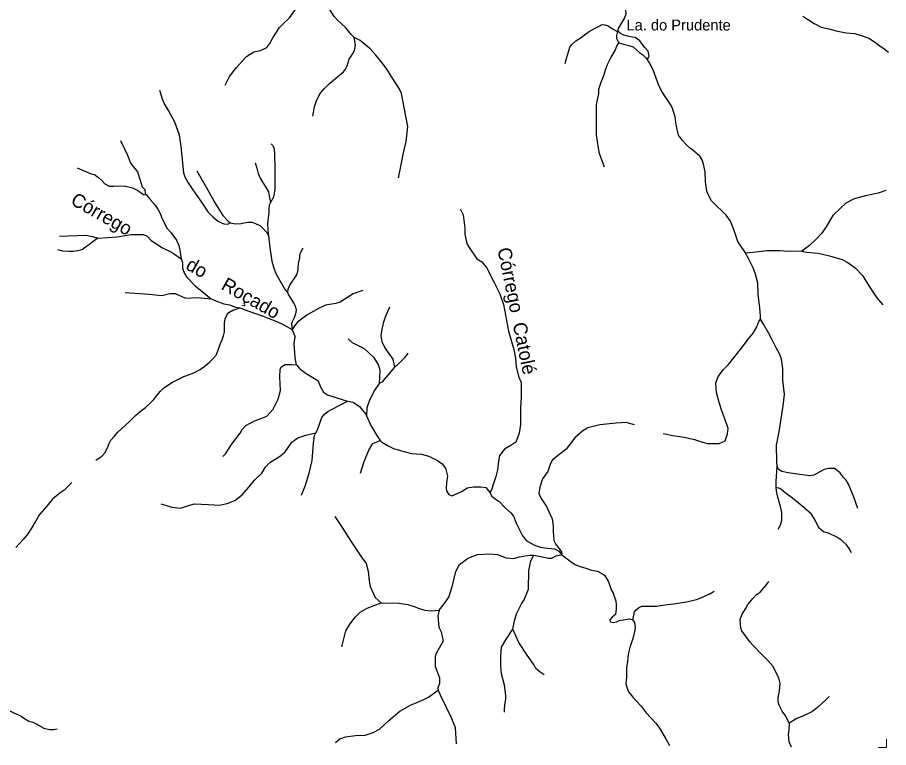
# Model space of a CAD drawing. Extents: x 717.8 to 772.7, y 8672.2 to 8728.
# Drawn here: x 759.54 to 772.27, y 8672.2 to 8682.87 of the extents above; entities that cross this region are included whole.
import ezdxf
from ezdxf.enums import TextEntityAlignment as Align

# ---------------------------------------------------------------- set-up
doc = ezdxf.new("R2010")
doc.units = 0
doc.header["$LTSCALE"] = 0.08
doc.linetypes.add('LONG_DASHED', pattern=[7.5, 6, -1.5])
for name, color, linetype, lineweight in [('3', 7, 'LONG_DASHED', 25), ('63', 7, 'Continuous', 13), ('9', 7, 'LONG_DASHED', 25)]:
    doc.layers.add(name, color=color, linetype=linetype, lineweight=lineweight)
doc.layers.add('61', color=7, linetype='Continuous')

msp = doc.modelspace()

# ---------------------------------------------------------------- linework, layer by layer
at = {"layer": '3'}
for points in [[(768.305, 8682.6583), (768.2931, 8682.6038), (768.2922, 8682.5588), (768.3145, 8682.5074), (768.3239, 8682.4937)], [(768.327, 8682.6503), (768.3193, 8682.6588), (768.305, 8682.6583)], [(768.7235, 8682.2744), (768.7408, 8682.267), (768.7583, 8682.2781), (768.7665, 8682.2996), (768.7658, 8682.3236), (768.7551, 8682.3746), (768.7062, 8682.4249), (768.672, 8682.4696), (768.634, 8682.5227), (768.5643, 8682.5714), (768.5192, 8682.5778), (768.4518, 8682.5927), (768.3969, 8682.6052), (768.3495, 8682.6303), (768.327, 8682.6503)], [(768.3239, 8682.4937), (768.3914, 8682.4758), (768.4691, 8682.4574), (768.5364, 8682.4339), (768.5888, 8682.3897), (768.6337, 8682.3497), (768.6735, 8682.3171), (768.716, 8682.282), (768.7235, 8682.2744)]]:
    msp.add_lwpolyline(points, dxfattribs=at)
at = {"layer": '63'}
msp.add_lwpolyline([(772.1148, 8672.1956), (772.238, 8672.1956), (772.238, 8672.317)], dxfattribs=at)
at = {"layer": '9'}
msp.add_line((761.4201, 8680.2721), (761.4742, 8680.2065), dxfattribs=at)
for points in [[(762.5702, 8681.8758), (762.6352, 8682.0036), (762.738, 8682.1322), (762.8845, 8682.2968), (762.988, 8682.3618), (763.0901, 8682.3839), (763.1789, 8682.4279), (763.2262, 8682.4867), (763.2673, 8682.5691), (763.3103, 8682.6356), (763.3634, 8682.7186), (763.4208, 8682.7739), (763.5135, 8682.8592), (763.586, 8682.9608), (763.6202, 8683.0225), (763.67, 8683.1221), (763.7067, 8683.1896), (763.7322, 8683.2728), (763.7626, 8683.3828), (763.7552, 8683.4633)], [(764.4569, 8682.5737), (764.4186, 8682.6102), (764.3323, 8682.7173), (764.2188, 8682.8192), (764.1669, 8682.8803), (764.0312, 8683.0871), (763.8813, 8683.2897), (763.785, 8683.3978), (763.7552, 8683.4633)], [(768.2321, 8683.4564), (768.2922, 8683.3015), (768.3226, 8683.2381), (768.4015, 8683.1162), (768.4239, 8682.9912), (768.4264, 8682.9122), (768.4077, 8682.86), (768.3189, 8682.7146), (768.305, 8682.6583)], [(771.0141, 8682.8855), (771.1809, 8682.777), (771.2831, 8682.7212), (771.3952, 8682.6987), (771.5005, 8682.6706), (771.6476, 8682.6429), (771.7766, 8682.6292), (771.8825, 8682.5953), (771.9786, 8682.5615), (772.0604, 8682.5109), (772.1392, 8682.4499), (772.2158, 8682.3983), (772.2674, 8682.3602)], [(767.5409, 8682.1933), (767.5584, 8682.2634), (767.5909, 8682.3612), (767.6092, 8682.4288), (767.6363, 8682.47), (767.6964, 8682.5242), (767.7765, 8682.5702), (767.8425, 8682.6238), (767.8929, 8682.6619), (767.9677, 8682.7021), (768.0376, 8682.7373), (768.0815, 8682.76), (768.121, 8682.7588), (768.1673, 8682.7423), (768.2341, 8682.6969), (768.305, 8682.6583)], [(763.8544, 8681.4228), (763.8782, 8681.5571), (763.9062, 8681.6485), (763.9559, 8681.7496), (764.0248, 8681.8289), (764.098, 8681.9013), (764.2991, 8682.0721), (764.3293, 8682.1105), (764.3527, 8682.1575), (764.3847, 8682.2551), (764.4322, 8682.3301), (764.4607, 8682.3835), (764.4745, 8682.4615), (764.4569, 8682.5737)], [(765.1044, 8680.5222), (765.1407, 8680.6872), (765.1758, 8680.8877), (765.2163, 8681.0509), (765.2395, 8681.272), (765.2133, 8681.4249), (765.1489, 8681.7531), (765.1163, 8681.8295), (765.0056, 8681.9938), (764.9365, 8682.1078), (764.8798, 8682.1828), (764.7731, 8682.3153), (764.6916, 8682.4058), (764.5422, 8682.5305), (764.4569, 8682.5737)], [(768.1148, 8680.6772), (768.0423, 8680.8769), (768.0302, 8680.9556), (768.0001, 8681.1493), (768.0004, 8681.3914), (768.0006, 8681.5912), (768.0339, 8681.7547), (768.032, 8681.8157), (768.0707, 8681.9339), (768.1018, 8682.0023), (768.136, 8682.1155), (768.1597, 8682.1764), (768.2119, 8682.2834), (768.268, 8682.3726), (768.297, 8682.4442), (768.3239, 8682.4937)], [(770.1763, 8679.4222), (770.1572, 8679.4562), (770.1106, 8679.5203), (770.0633, 8679.5926), (770.0154, 8679.7351), (769.9548, 8679.8868), (769.8914, 8679.9757), (769.8149, 8680.0544), (769.761, 8680.1032), (769.6795, 8680.1848), (769.6425, 8680.2572), (769.6117, 8680.3254), (769.592, 8680.4631), (769.5884, 8680.6082), (769.5632, 8680.7225), (769.5425, 8680.7867), (769.5095, 8680.8382), (769.4048, 8680.9258), (769.3515, 8680.9656), (769.3011, 8681.0161), (769.2558, 8681.0665), (769.1977, 8681.1434), (769.1618, 8681.2972), (769.1473, 8681.4126), (769.1103, 8681.5347), (769.0922, 8681.577), (768.9653, 8681.769), (768.9081, 8681.8699), (768.8307, 8682.0846), (768.7855, 8682.1786), (768.7389, 8682.2566), (768.7235, 8682.2744)], [(761.6136, 8681.805), (761.6493, 8681.6753), (761.687, 8681.5913), (761.7432, 8681.5), (761.8298, 8681.3415), (761.9006, 8681.15), (761.9244, 8680.9787), (761.9635, 8680.5934), (761.9807, 8680.5345), (762.0283, 8680.4472), (762.1004, 8680.3466), (762.2003, 8680.2022), (762.2625, 8680.1076), (762.318, 8680.0269), (762.3949, 8679.9472), (762.4716, 8679.8811), (762.5536, 8679.8493), (762.6118, 8679.8427), (762.6451, 8679.8663)], [(761.0401, 8681.0651), (761.1439, 8680.8542), (761.1883, 8680.7383), (761.2906, 8680.6099), (761.3246, 8680.5005), (761.3575, 8680.3882), (761.3986, 8680.3534), (761.4029, 8680.2948), (761.4201, 8680.2721)], [(763.243, 8681.018), (763.2646, 8681.0001), (763.2834, 8680.9633), (763.2942, 8680.8932), (763.2988, 8680.6266), (763.2952, 8680.4965), (763.295, 8680.3573), (763.2757, 8680.2401), (763.2332, 8680.1618)], [(763.0086, 8680.7416), (763.0337, 8680.6614), (763.0561, 8680.5863), (763.0839, 8680.5174), (763.111, 8680.4693), (763.1596, 8680.3915), (763.2062, 8680.3158), (763.2211, 8680.2281), (763.2332, 8680.1618)], [(760.4075, 8680.67), (760.6152, 8680.5807), (760.6617, 8680.5703), (760.7243, 8680.5239), (760.7682, 8680.4822), (760.8115, 8680.4336), (760.8783, 8680.4007), (760.9378, 8680.3981), (761.0971, 8680.4029), (761.2153, 8680.3774), (761.296, 8680.3355), (761.3757, 8680.2785), (761.4201, 8680.2721)], [(762.1559, 8680.6225), (762.234, 8680.4895), (762.331, 8680.3155), (762.4168, 8680.1658), (762.5391, 8679.9697), (762.6094, 8679.8949), (762.6451, 8679.8663)], [(772.2276, 8680.3388), (772.1167, 8680.2998), (771.9319, 8680.2604), (771.7646, 8680.2161), (771.6429, 8680.1491), (771.5657, 8680.0799), (771.4542, 8679.9698), (771.3457, 8679.7899), (771.2867, 8679.7075), (771.2002, 8679.6149), (771.1094, 8679.5336), (771.0019, 8679.4507)], [(761.4742, 8680.2065), (761.5485, 8680.1207), (761.5872, 8680.065), (761.6271, 8679.9898), (761.6464, 8679.9328), (761.6796, 8679.8671), (761.7176, 8679.7864)], [(763.2332, 8680.1618), (763.2153, 8680.1198), (763.2092, 8680.0619), (763.2112, 8680.0185), (763.1923, 8679.849), (763.1974, 8679.7508), (763.203, 8679.6743)], [(766.0073, 8680.0694), (766.0478, 8679.9795), (766.0751, 8679.7883), (766.0752, 8679.7002), (766.1052, 8679.5618), (766.136, 8679.5046), (766.2517, 8679.3403), (766.321, 8679.2957), (766.3924, 8679.2129), (766.5043, 8678.9943), (766.5844, 8678.8286), (766.6382, 8678.6682), (766.7113, 8678.2787), (766.7897, 8678.0118), (766.8152, 8677.8875), (766.8258, 8677.758), (766.8619, 8677.6108), (766.8962, 8677.5323), (766.8971, 8677.3226), (766.8865, 8677.1622), (766.8856, 8677.0565), (766.8865, 8676.9172), (766.8689, 8676.7921), (766.8204, 8676.6581), (766.7447, 8676.6105), (766.6522, 8676.5576), (766.5817, 8676.4642), (766.564, 8676.3797), (766.5508, 8676.2537), (766.5297, 8676.1585), (766.4909, 8676.0528), (766.4645, 8675.9602), (766.4419, 8675.9219)], [(762.6451, 8679.8663), (762.7243, 8679.8506), (762.8067, 8679.8552), (762.8966, 8679.8745), (762.9595, 8679.8724), (763.0141, 8679.8522), (763.0856, 8679.8201), (763.1042, 8679.8074), (763.1864, 8679.7193), (763.203, 8679.6743)], [(761.7176, 8679.7864), (761.7837, 8679.7156), (761.8609, 8679.6125), (761.8952, 8679.5325), (761.9068, 8679.4648), (761.9301, 8679.3364)], [(760.7104, 8679.6411), (760.6213, 8679.5762), (760.5876, 8679.5471), (760.5325, 8679.5073), (760.488, 8679.4766), (760.4205, 8679.4558), (760.3517, 8679.446), (760.2873, 8679.4444), (760.2007, 8679.4511), (760.1234, 8679.4713)], [(760.1525, 8679.6675), (760.5363, 8679.6851), (760.6313, 8679.6667), (760.7104, 8679.6411)], [(760.7104, 8679.6411), (760.9912, 8679.6572), (761.1975, 8679.694), (761.3793, 8679.6958), (761.4311, 8679.668), (761.4914, 8679.6058), (761.6568, 8679.4966), (761.7849, 8679.4336), (761.8445, 8679.3963), (761.9301, 8679.3364)], [(763.203, 8679.6743), (763.2258, 8679.5039), (763.2544, 8679.3046), (763.2831, 8679.2012), (763.316, 8679.1137), (763.4467, 8678.8872), (763.4837, 8678.8482)], [(763.7068, 8679.4923), (763.6708, 8679.4322), (763.6581, 8679.3919), (763.6586, 8679.3534), (763.6371, 8679.272), (763.633, 8679.2023), (763.6304, 8679.1523), (763.6151, 8679.1046), (763.5728, 8679.0473), (763.5403, 8678.9974), (763.5201, 8678.9662), (763.4877, 8678.8924), (763.4837, 8678.8482)], [(771.0019, 8679.4507), (770.8057, 8679.4447), (770.6741, 8679.4543), (770.4951, 8679.4548), (770.285, 8679.4314), (770.1763, 8679.4222)], [(771.0019, 8679.4507), (771.0694, 8679.4342), (771.2369, 8679.4189), (771.4052, 8679.381), (771.5873, 8679.3271), (771.6731, 8679.2864), (771.7838, 8679.2033), (771.8843, 8679.094), (771.9908, 8678.9264), (772.0549, 8678.8273), (772.0956, 8678.7699), (772.182, 8678.6655)], [(761.9301, 8679.3364), (761.9454, 8679.2793), (761.9501, 8679.2033), (761.9732, 8679.131), (762.005, 8679.076), (762.1341, 8678.9454), (762.3691, 8678.7526)], [(770.3976, 8678.4546), (770.3947, 8678.5031), (770.3866, 8678.6147), (770.3638, 8678.8207), (770.3561, 8678.9823), (770.3208, 8679.1123), (770.2871, 8679.2088), (770.2211, 8679.341), (770.1763, 8679.4222)], [(761.1098, 8678.8469), (761.4593, 8678.8198), (761.6445, 8678.8024), (761.7616, 8678.8322), (761.8389, 8678.8322), (761.9898, 8678.762), (762.1695, 8678.7724), (762.3691, 8678.7526)], [(763.4837, 8678.8482), (763.4998, 8678.8045), (763.5719, 8678.6943), (763.5941, 8678.6493), (763.6081, 8678.5878), (763.6005, 8678.5355), (763.5779, 8678.4755), (763.5515, 8678.4191), (763.5428, 8678.3884), (763.5488, 8678.3038)], [(764.5811, 8678.8758), (764.4427, 8678.8241), (764.2526, 8678.7032), (764.189, 8678.6829), (764.0402, 8678.6584), (763.9255, 8678.6059), (763.7641, 8678.5137), (763.6285, 8678.4123), (763.5837, 8678.3612), (763.5488, 8678.3038)], [(762.3691, 8678.7526), (762.4341, 8678.723), (762.5531, 8678.6818), (762.6352, 8678.6662), (762.7214, 8678.6324), (762.7889, 8678.6222)], [(760.6799, 8676.3948), (760.7699, 8676.455), (760.815, 8676.5049), (760.85, 8676.5776), (760.8751, 8676.6377), (760.9001, 8676.6878), (760.9476, 8676.7429), (761.0028, 8676.8054), (761.0603, 8676.858), (761.1078, 8676.903), (761.1704, 8676.9555), (761.2254, 8677.013), (761.263, 8677.0504), (761.3281, 8677.1054), (761.4081, 8677.1654), (761.4769, 8677.228), (761.5294, 8677.2805), (761.5721, 8677.3405), (761.6246, 8677.403), (761.6697, 8677.448), (761.7197, 8677.483), (761.8023, 8677.5353), (761.8798, 8677.5752), (761.9674, 8677.6177), (762.0524, 8677.6475), (762.1124, 8677.6724), (762.2063, 8677.7224), (762.2789, 8677.7723), (762.3489, 8677.8323), (762.3965, 8677.8797), (762.4391, 8677.9321), (762.4742, 8678.0172), (762.5018, 8678.0997), (762.527, 8678.1547), (762.5471, 8678.2122), (762.5596, 8678.2722), (762.5622, 8678.3198), (762.5623, 8678.3974), (762.5711, 8678.4601), (762.5937, 8678.5126), (762.6238, 8678.5524), (762.6838, 8678.5899), (762.7889, 8678.6222)], [(762.7889, 8678.6222), (762.8633, 8678.5935), (762.9986, 8678.5417), (763.126, 8678.5013), (763.1993, 8678.4691), (763.2641, 8678.4449), (763.3281, 8678.4209), (763.4179, 8678.3807), (763.5488, 8678.3038)], [(764.9753, 8678.6338), (764.9077, 8678.4856), (764.8786, 8678.3985), (764.8574, 8678.2793), (764.8443, 8678.2176), (764.8627, 8678.1227), (764.9137, 8678.0243), (764.9593, 8677.9603), (765.0234, 8677.8701), (765.0464, 8677.7553)], [(768.9738, 8676.7849), (769.1136, 8676.7546), (769.279, 8676.7325), (769.4314, 8676.6978), (769.5489, 8676.6596), (769.6143, 8676.6417), (769.7934, 8676.6369), (769.8795, 8676.6803), (769.9139, 8676.7795), (769.9249, 8676.8608), (769.875, 8677.0005), (769.8296, 8677.1176), (769.7896, 8677.2361), (769.7519, 8677.386), (769.7422, 8677.5224), (769.7767, 8677.6161), (769.8546, 8677.7229), (769.9289, 8677.7918), (770.0026, 8677.8848), (770.1146, 8678.0266), (770.222, 8678.1692), (770.2859, 8678.2511), (770.3406, 8678.3435), (770.37, 8678.4201), (770.3976, 8678.4546)], [(770.6368, 8676.3061), (770.6329, 8676.3718), (770.6296, 8676.6147), (770.6662, 8676.8118), (770.728, 8677.1896), (770.7453, 8677.3547), (770.7227, 8677.5635), (770.72, 8677.7366), (770.7027, 8677.871), (770.6768, 8677.9383), (770.6263, 8678.0387), (770.5704, 8678.1432), (770.5112, 8678.257), (770.4379, 8678.384), (770.3976, 8678.4546)], [(763.6138, 8677.7879), (763.5964, 8677.8892), (763.5775, 8678.1025), (763.595, 8678.1997), (763.5761, 8678.2514), (763.5488, 8678.3038)], [(764.3707, 8678.1674), (764.4264, 8678.1136), (764.6027, 8678.0282), (764.7413, 8677.9018), (764.8056, 8677.792), (764.8322, 8677.7121), (764.824, 8677.5165)], [(765.2417, 8677.9607), (765.1912, 8677.8896), (765.0762, 8677.7733), (765.0464, 8677.7553)], [(762.5375, 8676.4513), (762.5792, 8676.4942), (762.6102, 8676.5414), (762.663, 8676.6253), (762.7898, 8676.7925), (762.8221, 8676.8459), (762.8712, 8676.9006), (762.9977, 8676.9692), (763.1241, 8677.0148), (763.1816, 8677.0376), (763.2738, 8677.1417), (763.3471, 8677.2859), (763.3782, 8677.4127), (763.372, 8677.6083), (763.3745, 8677.7269), (763.3925, 8677.7587), (763.4422, 8677.796), (763.5387, 8677.7935), (763.6138, 8677.7879)], [(763.6138, 8677.7879), (763.6639, 8677.7282), (763.7566, 8677.664), (763.9246, 8677.559), (763.9681, 8677.4571), (764.0079, 8677.39), (764.065, 8677.349), (764.2983, 8677.2788), (764.358, 8677.26)], [(765.0464, 8677.7553), (764.9434, 8677.6307), (764.863, 8677.5372), (764.824, 8677.5165)], [(764.824, 8677.5165), (764.7598, 8677.4228), (764.6801, 8677.2719), (764.6428, 8677.1626), (764.6373, 8677.0428)], [(763.8974, 8676.7974), (763.9214, 8676.8389), (763.9849, 8677.0194), (764.0279, 8677.071), (764.0708, 8677.1082), (764.1231, 8677.1358), (764.258, 8677.2032), (764.358, 8677.26)], [(764.358, 8677.26), (764.4422, 8677.2412), (764.5334, 8677.1824), (764.6232, 8677.0726), (764.6373, 8677.0428)], [(764.6373, 8677.0428), (764.7003, 8676.9047), (764.7899, 8676.7584), (764.8351, 8676.6853)], [(768.5553, 8676.9137), (768.4303, 8676.9466), (768.2875, 8676.9383), (768.0469, 8676.9137), (767.8716, 8676.8687), (767.8003, 8676.8264), (767.6823, 8676.7208), (767.5541, 8676.5571), (767.3509, 8676.3937), (767.3201, 8676.332), (767.2892, 8676.228), (767.2117, 8676.1205), (767.1695, 8676.0011), (767.1572, 8675.9091), (767.1911, 8675.8371), (767.2683, 8675.7187), (767.3484, 8675.539), (767.366, 8675.4341), (767.3642, 8675.3557), (767.3748, 8675.2226), (767.4003, 8675.1715), (767.4889, 8675.0554), (767.4914, 8675.0128)], [(761.6335, 8675.7578), (761.7907, 8675.7084), (761.9198, 8675.6935), (762.0371, 8675.7319), (762.124, 8675.7553), (762.3274, 8675.7487), (762.4869, 8675.7405), (762.6004, 8675.7632), (762.7144, 8675.8076), (762.818, 8675.8878), (762.9196, 8676.0026), (763.0017, 8676.1052), (763.1074, 8676.2045), (763.1583, 8676.2875), (763.2263, 8676.3603), (763.3813, 8676.461), (763.4503, 8676.5182), (763.5471, 8676.6592), (763.6332, 8676.7202), (763.7491, 8676.7588), (763.8974, 8676.7974)], [(763.6871, 8675.8823), (763.7454, 8676.028), (763.8009, 8676.2064), (763.8406, 8676.3916), (763.8637, 8676.6429), (763.8793, 8676.7564), (763.8974, 8676.7974)], [(764.5474, 8676.2071), (764.6007, 8676.3768), (764.6716, 8676.5432), (764.7281, 8676.6397), (764.8351, 8676.6853)], [(764.8351, 8676.6853), (764.8592, 8676.6601), (764.9419, 8676.6104), (765.0317, 8676.5655), (765.183, 8676.5206), (765.2964, 8676.4934), (765.4403, 8676.4838), (765.5473, 8676.4553), (765.677, 8676.3917), (765.7408, 8676.3409), (765.7939, 8676.2794), (765.8223, 8676.1612), (765.8068, 8676.0663), (765.7999, 8675.9888), (765.8079, 8675.9476), (765.8426, 8675.8937), (765.8848, 8675.8749), (765.9645, 8675.907), (766.0312, 8675.9396), (766.1098, 8675.9925), (766.201, 8676.0083), (766.2627, 8676.0069), (766.3077, 8676.0069), (766.3808, 8675.9955), (766.4419, 8675.9219)], [(770.6224, 8675.9964), (770.6269, 8676.083), (770.6368, 8676.3061)], [(771.819, 8675.687), (771.7535, 8675.8696), (771.6826, 8676.043), (771.6473, 8676.1022), (771.606, 8676.1488), (771.5588, 8676.2094), (771.475, 8676.2759), (771.3872, 8676.2732), (771.3253, 8676.2606), (771.2209, 8676.2001), (771.1737, 8676.1788), (771.1145, 8676.1688), (770.9701, 8676.1848), (770.8005, 8676.2094), (770.7089, 8676.2298), (770.656, 8676.2641), (770.6368, 8676.3061)], [(760.3306, 8676.0713), (760.2176, 8675.9583), (760.1591, 8675.9181), (760.0461, 8675.8242), (759.9665, 8675.7234), (759.8578, 8675.6002), (759.7666, 8675.4416), (759.6886, 8675.3195), (759.6173, 8675.2349), (759.5096, 8675.1195)], [(766.4419, 8675.9219), (766.467, 8675.8694), (766.5162, 8675.8287), (766.5739, 8675.7935), (766.6627, 8675.6987), (766.7483, 8675.6274), (766.784, 8675.5774), (766.8186, 8675.491), (766.8582, 8675.4065), (766.9116, 8675.3018), (766.9704, 8675.2237), (767.0804, 8675.1596), (767.1755, 8675.1252), (767.2433, 8675.1146), (767.3337, 8675.1068), (767.3837, 8675.0997), (767.4469, 8675.0671), (767.4914, 8675.0128)], [(771.7242, 8675.0425), (771.6907, 8675.1063), (771.6516, 8675.1573), (771.5842, 8675.2206), (771.509, 8675.2706), (771.3908, 8675.3288), (771.3154, 8675.3489), (771.2487, 8675.4071), (771.196, 8675.5168), (771.1415, 8675.6089), (771.0301, 8675.7063), (770.8642, 8675.8403), (770.7747, 8675.9024), (770.6792, 8675.9827), (770.6224, 8675.9964)], [(770.6545, 8675.3875), (770.692, 8675.4546), (770.706, 8675.5184), (770.7049, 8675.6301), (770.6859, 8675.718), (770.6481, 8675.8545), (770.6351, 8675.9116), (770.6224, 8675.9964)], [(764.1766, 8675.5736), (764.2834, 8675.4107), (764.4079, 8675.2099), (764.5661, 8674.978), (764.6298, 8674.8862), (764.6616, 8674.7719), (764.6771, 8674.6328), (764.6916, 8674.5508), (764.7627, 8674.3897), (764.8519, 8674.3101)], [(766.1581, 8674.9789), (766.2586, 8675.0177), (766.4403, 8675.0293), (766.5538, 8675.0181), (766.6776, 8674.9693), (766.7855, 8674.9607), (766.8717, 8674.9843), (766.9522, 8674.996), (767.0308, 8675.0062), (767.0808, 8675.0052)], [(766.775, 8673.9281), (766.8023, 8674.048), (766.8283, 8674.152), (766.9009, 8674.2957), (766.9406, 8674.3531), (767.0033, 8674.5083), (767.0116, 8674.7798), (767.039, 8674.9225), (767.0808, 8675.0052)], [(767.0808, 8675.0052), (767.2997, 8674.9648), (767.3464, 8674.9657), (767.4111, 8674.9963), (767.4542, 8675.0054), (767.4914, 8675.0128)], [(767.4914, 8675.0128), (767.5488, 8674.9676), (767.6312, 8674.9074), (767.6863, 8674.8722), (767.7437, 8674.8472), (767.8411, 8674.8171), (767.9261, 8674.787), (768.011, 8674.7719), (768.0759, 8674.7418), (768.1133, 8674.7166), (768.1674, 8674.6291), (768.1921, 8674.5633), (768.215, 8674.5022), (768.2422, 8674.4527), (768.2621, 8674.3924), (768.2796, 8674.3396), (768.2846, 8674.2818), (768.2847, 8674.2215), (768.2742, 8674.1399), (768.2297, 8674.1033), (768.1947, 8674.063), (768.1993, 8674.0332), (768.2407, 8674.0253), (768.2944, 8674.0332), (768.3323, 8674.0526), (768.3896, 8674.0606), (768.4812, 8674.0791), (768.5296, 8674.0606), (768.5303, 8674.0594)], [(765.7008, 8674.2057), (765.7591, 8674.2777), (765.8386, 8674.3916), (765.8954, 8674.5623), (765.9407, 8674.7672), (765.9975, 8674.8696), (766.111, 8674.9607), (766.1581, 8674.9789)], [(770.3895, 8674.4684), (770.4718, 8674.5629), (770.5151, 8674.6212)], [(768.5303, 8674.0594), (768.5434, 8674.1311), (768.5534, 8674.1789), (768.5784, 8674.2091), (768.6133, 8674.2392), (768.6609, 8674.2618), (768.7283, 8674.2644), (768.8158, 8674.2618), (768.8758, 8674.2618), (768.9358, 8674.272), (769.0358, 8674.2871), (769.1305, 8674.2967), (769.2234, 8674.3097), (769.3164, 8674.3266), (769.4609, 8674.3619), (769.5454, 8674.3945), (769.5862, 8674.4128), (769.6537, 8674.443), (769.7172, 8674.4791)], [(770.8157, 8672.5513), (770.7679, 8672.657), (770.7144, 8672.7257), (770.6677, 8672.8136), (770.6545, 8672.8654), (770.655, 8672.9266), (770.6736, 8673.0254), (770.6842, 8673.1306), (770.6622, 8673.2118), (770.5808, 8673.3825), (770.5035, 8673.4662), (770.4121, 8673.5611), (770.2892, 8673.6859), (770.2391, 8673.7432), (770.1769, 8673.8273), (770.1219, 8673.9002), (770.1069, 8673.9413), (770.1014, 8674.0097), (770.1003, 8674.0658), (770.1247, 8674.1359), (770.1747, 8674.2215), (770.2106, 8674.2868), (770.2895, 8674.3811), (770.3345, 8674.4267), (770.3895, 8674.4684)], [(764.2759, 8673.6684), (764.3352, 8673.9008), (764.3966, 8674.0038), (764.4761, 8674.1064), (764.5442, 8674.1746), (764.6464, 8674.2316), (764.8519, 8674.3101)], [(764.8519, 8674.3101), (765.1081, 8674.3053), (765.2412, 8674.2885), (765.3336, 8674.2585), (765.4044, 8674.2261), (765.4884, 8674.2045), (765.5808, 8674.1961), (765.7008, 8674.2057)], [(765.7008, 8674.2057), (765.678, 8674.1205), (765.6937, 8673.9572), (765.7273, 8673.8852), (765.7592, 8673.7527), (765.7009, 8673.6463), (765.657, 8673.5705), (765.6396, 8673.5238), (765.642, 8673.3821), (765.7045, 8673.2165)], [(768.5303, 8674.0594), (768.5521, 8674.0228), (768.5646, 8673.9575), (768.5571, 8673.9097), (768.5359, 8673.8041), (768.5109, 8673.7312), (768.486, 8673.6558), (768.4685, 8673.5802), (768.4585, 8673.5173), (768.451, 8673.4469), (768.4385, 8673.3638), (768.4385, 8673.2884), (768.436, 8673.223), (768.4273, 8673.1249), (768.4447, 8673.0645), (768.4657, 8673.0124), (768.5297, 8672.9336), (768.5872, 8672.8682), (768.6522, 8672.8004), (768.7246, 8672.7022), (768.8636, 8672.55), (768.9191, 8672.4778), (769.0134, 8672.3225), (769.0645, 8672.224)], [(766.6524, 8672.7111), (766.6529, 8672.7604), (766.664, 8672.8503), (766.6752, 8672.904), (766.6741, 8672.9577), (766.6527, 8673.1072), (766.612, 8673.275), (766.6003, 8673.3921), (766.5994, 8673.5372), (766.6107, 8673.6625), (766.6726, 8673.7708), (766.775, 8673.9281)], [(767.2321, 8673.2605), (767.174, 8673.2957), (767.1143, 8673.3531), (767.0884, 8673.3989), (766.9775, 8673.5595), (766.8654, 8673.7328), (766.775, 8673.9281)], [(765.7045, 8673.2165), (765.7045, 8673.1396), (765.6981, 8673.1177), (765.6918, 8673.0985), (765.6912, 8673.0963), (765.6815, 8673.0622), (765.685, 8673.0377)], [(764.1862, 8672.271), (764.248, 8672.3215), (764.329, 8672.3509), (764.4766, 8672.3737), (764.6184, 8672.3793), (764.7368, 8672.4171), (764.8284, 8672.4649), (764.9647, 8672.5904), (765.1224, 8672.7291), (765.2796, 8672.8167), (765.3733, 8672.8527), (765.4755, 8672.8983), (765.5436, 8672.9325), (765.6685, 8673.0237), (765.685, 8673.0377)], [(765.9517, 8672.2525), (765.9373, 8672.4854), (765.8737, 8672.6402), (765.8053, 8672.7819), (765.7202, 8672.9591), (765.685, 8673.0377)], [(758.9345, 8672.9025), (759.066, 8672.8701), (759.1898, 8672.8273), (759.3908, 8672.749), (759.5376, 8672.6802)], [(771.4004, 8672.9425), (771.349, 8672.8924), (771.232, 8672.7854), (771.1538, 8672.7208), (771.0139, 8672.6534), (770.9255, 8672.6192), (770.8157, 8672.5513)], [(759.5376, 8672.6802), (759.5729, 8672.6627), (759.6397, 8672.6229), (759.7006, 8672.5831), (759.7585, 8672.5655)], [(759.7585, 8672.5655), (759.8091, 8672.5437), (759.9194, 8672.4785), (760.0037, 8672.4588), (760.0686, 8672.4587), (760.114, 8672.4717)], [(770.8157, 8672.5513), (770.8104, 8672.448), (770.8014, 8672.3886), (770.8119, 8672.2826), (770.843, 8672.2085)]]:
    msp.add_lwpolyline(points, dxfattribs=at)

# ---------------------------------------------------------------- texts
at = {"layer": '61'}
msp.add_text('La. do Prudente', height=0.16, dxfattribs=at).set_placement((768.4373, 8682.6748))
for s, rotation, p in [('Córrego             do    Roçado', 330.579, (761.7997, 8679.2974)), ('Córrego  Catolé', 281.563, (766.7384, 8678.5568))]:
    msp.add_text(s, height=0.2, rotation=rotation, dxfattribs=at).set_placement(p, align=Align.CENTER)

doc.saveas('drawing.dxf')
